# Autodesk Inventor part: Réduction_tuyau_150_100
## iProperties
Shininess: 64.0
Length Units: 11269
Angle Units: 11279
Time Units: 11290
Mass Units: 11283
Length Display Precision: 3
Angle Display Precision: 2
Compacted: True
Part Number: Réduction_tuyau_150_100
Document SubType Name: Modeling
Created: 2008-04
Material: Par défaut
Designer: plup
Density: 0.0
Volumn: 0.0
Area: 0.0
PropertySet Name: Model Information
Control State: 0
Master: False
Checked Out: False
MATIERE_PIECE: X2CrNi 18-11
DESIGNATION: Réduction DN150 DN100
Author: plup
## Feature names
1. Révolution1 [Revolution]
